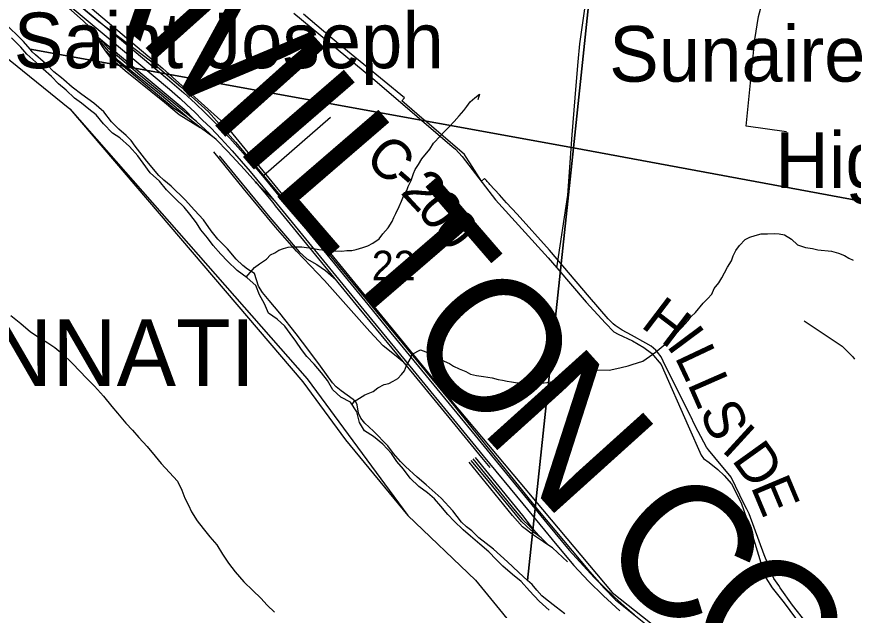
# Model space of a CAD drawing. Extents: x 0 to 34, y 0 to 22.
# Drawn here: x 5.729 to 6.917, y 14.739 to 15.582 of the extents above; entities that cross this region are included whole.
import ezdxf

# ---------------------------------------------------------------- set-up
doc = ezdxf.new("R2010")
doc.units = 0
for name, color, linetype in [('GM_X_City_Street', 7, 'Continuous'), ('GM_X_Corporation', 7, 'Continuous'), ('GM_X_Corporation_Text', 7, 'Continuous'), ('GM_X_County_Road', 7, 'Continuous'), ('GM_X_County_Road_Text', 7, 'Continuous'), ('GM_X_County_Text', 7, 'Continuous'), ('GM_X_Major_River', 7, 'Continuous'), ('GM_X_Minor_River', 7, 'Continuous'), ('GM_X_Rail_Line', 7, 'Continuous'), ('GM_X_Section_Text', 7, 'Continuous'), ('GM_X_Township_Road', 7, 'Continuous'), ('GM_X_Unincorporated_Text', 7, 'Continuous'), ('GM_X_US_Route', 7, 'Continuous')]:
    doc.layers.add(name, color=color, linetype=linetype)

msp = doc.modelspace()

# ---------------------------------------------------------------- linework, layer by layer
at = {"layer": 'GM_X_City_Street'}
msp.add_line((6.0794, 15.3568), (6.1746, 15.4398), dxfattribs=at)
at = {"layer": 'GM_X_Corporation'}
for points in [[(3.3535, 16.9293), (3.4766, 16.7367), (3.5579, 16.6419), (3.619, 16.5459), (3.7774, 16.2543), (3.8686, 16.1561), (3.9643, 16.0792), (4.2564, 15.9374), (4.3533, 15.9108), (4.4487, 15.8964), (4.6416, 15.8532), (4.7366, 15.8475), (5.0291, 15.8581), (5.1241, 15.8236), (5.4143, 15.7071), (5.7095, 15.5281), (5.8045, 15.4515), (6.1414, 15.0678), (6.2843, 14.8736), (6.3804, 14.7819), (6.459, 14.6859)], [(3.3535, 16.9293), (3.4766, 16.7367), (3.5579, 16.6419), (3.619, 16.5459), (3.7774, 16.2543), (3.8686, 16.1561), (3.9643, 16.0792), (4.2564, 15.9374), (4.3533, 15.9108), (4.4487, 15.8964), (4.6416, 15.8532), (4.7366, 15.8475), (5.0291, 15.8581), (5.1241, 15.8236), (5.4143, 15.7071), (5.7095, 15.5281), (5.8045, 15.4515), (6.1354, 15.0636), (6.1959, 14.9814), (6.2842, 14.8736), (6.3804, 14.7819), (6.459, 14.6859)], [(3.3535, 16.9293), (3.4766, 16.7367), (3.5579, 16.6419), (3.619, 16.5459), (3.7774, 16.2543), (3.8686, 16.1561), (3.9643, 16.0792), (4.2564, 15.9374), (4.3533, 15.9108), (4.4487, 15.8964), (4.6416, 15.8532), (4.7366, 15.8475), (5.0291, 15.8581), (5.1241, 15.8236), (5.4143, 15.7071), (5.7095, 15.5281), (5.8045, 15.4515), (6.1414, 15.0678), (6.2843, 14.8736), (6.3804, 14.7819), (6.459, 14.6859)], [(6.8502, 14.7219), (6.8308, 14.7465), (6.8133, 14.7711), (6.8111, 14.7743), (6.8041, 14.7841), (6.7996, 14.7951), (6.7955, 14.8053), (6.7903, 14.818), (6.769, 14.876), (6.7657, 14.8828), (6.7622, 14.8899), (6.7437, 14.9281), (6.7299, 14.9448), (6.7294, 14.9454), (6.7115, 14.9671), (6.7084, 14.971), (6.6966, 14.993), (6.691, 15.0041), (6.6865, 15.0133), (6.686, 15.0143), (6.6804, 15.0254), (6.6471, 15.093), (6.6439, 15.099), (6.639, 15.1059), (6.6366, 15.1085), (6.6334, 15.1114), (6.6297, 15.1142), (6.6222, 15.1186), (6.6021, 15.1298), (6.5887, 15.1372), (6.5828, 15.1407), (6.5788, 15.1436), (6.5757, 15.1461), (6.5687, 15.153), (6.5424, 15.184), (6.4856, 15.2508), (6.4394, 15.3019), (6.4246, 15.3181), (6.4145, 15.3292), (6.401, 15.344), (6.3997, 15.3454), (6.3984, 15.3468), (6.3971, 15.3483), (6.3958, 15.3497), (6.3945, 15.3511), (6.3933, 15.3525), (6.389, 15.3487), (6.3722, 15.375), (6.3715, 15.3761), (6.3713, 15.3763), (6.367, 15.3831), (6.3647, 15.3868), (6.3112, 15.4324), (6.3041, 15.4384), (6.2756, 15.4628), (6.2794, 15.467), (6.222, 15.5144), (6.1857, 15.5437), (6.1644, 15.5619), (6.1363, 15.5862)], [(6.5071, 14.734), (6.4952, 14.7437), (6.48, 14.7555), (6.4748, 14.7598), (6.4674, 14.7675), (6.4608, 14.776), (6.4541, 14.7815), (6.5194, 15.3963), (7.5438, 15.2065), (7.4624, 14.2167)]]:
    msp.add_lwpolyline(points, dxfattribs=at)
for points in [[(6.6267, 16.412), (6.5194, 15.3963), (5.7481, 15.5362), (5.7385, 15.5474), (5.73, 15.556), (5.7193, 15.5661), (5.7119, 15.5735), (5.7045, 15.5805), (5.6956, 15.5879), (5.6844, 15.5969), (5.6733, 15.6058), (5.6644, 15.6136), (5.6543, 15.6226), (5.6473, 15.6288), (5.6384, 15.6362), (5.6358, 15.6382), (5.7092, 16.4608)], [(7.6501, 16.2281), (7.5438, 15.2065), (6.5194, 15.3963), (6.6267, 16.412)], [(6.5194, 15.3963), (6.4541, 14.7815), (6.4415, 14.7932), (6.426, 14.8079), (6.4059, 14.8262), (6.3851, 14.8419), (6.3751, 14.852), (6.3677, 14.8578), (6.3607, 14.8644), (6.3482, 14.8803), (6.3316, 14.8985), (6.3104, 14.9176), (6.2974, 14.9285), (6.2811, 14.9433), (6.2741, 14.9503), (6.2641, 14.9619), (6.2561, 14.9727), (6.2354, 14.9936), (6.2231, 15.0049), (6.2176, 15.0123), (6.2144, 15.0192), (6.2124, 15.0309), (6.2106, 15.0351), (6.2069, 15.0386), (6.1894, 15.0508), (6.1827, 15.0567), (6.1772, 15.0625), (6.1603, 15.086), (6.1438, 15.108), (6.1258, 15.1319), (6.1027, 15.1613), (6.0876, 15.1794), (6.078, 15.1907), (6.0722, 15.1995), (6.0665, 15.2178), (6.0568, 15.2238), (6.0498, 15.2292), (6.0405, 15.2378), (6.0284, 15.2529), (6.0224, 15.2583), (6.0147, 15.2665), (6.0051, 15.2781), (5.9941, 15.2938), (5.9812, 15.3074), (5.9679, 15.3225), (5.9483, 15.3419), (5.9379, 15.3501), (5.9309, 15.3568), (5.9136, 15.3773), (5.897, 15.3985), (5.8916, 15.4066), (5.8845, 15.4136), (5.8738, 15.4229), (5.8634, 15.433), (5.8524, 15.4473), (5.8383, 15.4594), (5.8215, 15.4719), (5.8074, 15.4825), (5.7959, 15.493), (5.7926, 15.4957), (5.7814, 15.504), (5.7718, 15.5144), (5.7666, 15.5187), (5.7555, 15.5281), (5.7507, 15.5327), (5.7481, 15.5362)]]:
    msp.add_lwpolyline(points, close=True, dxfattribs=at)
at = {"layer": 'GM_X_County_Road'}
for points in [[(6.5262, 15.5183), (6.5284, 15.5439), (6.5532, 15.7171)], [(6.1224, 15.5873), (6.2346, 15.4946), (6.347, 15.3985), (6.3522, 15.3945), (6.3615, 15.3837), (6.4087, 15.3224), (6.4835, 15.24), (6.4957, 15.2258), (6.5378, 15.177), (6.5652, 15.1472), (6.5771, 15.1348), (6.5831, 15.1316), (6.6034, 15.1221), (6.6195, 15.1123), (6.6303, 15.1044), (6.644, 15.0882), (6.6823, 15.0013), (6.7011, 14.9596), (6.7044, 14.9549), (6.7122, 14.9491), (6.7245, 14.9393), (6.7334, 14.9308), (6.7438, 14.9188), (6.7576, 14.8916), (6.774, 14.8454), (6.7889, 14.7957), (6.7928, 14.7854), (6.8016, 14.7712), (6.8186, 14.7496), (6.8606, 14.6933)], [(6.4957, 15.2258), (6.5116, 15.3289), (6.5175, 15.4145), (6.5233, 15.4846), (6.5262, 15.5183)]]:
    msp.add_lwpolyline(points, dxfattribs=at)
at = {"layer": 'GM_X_Major_River'}
for points in [[(5.9843, 15.2894), (5.9747, 15.3017), (5.9669, 15.3121), (5.9545, 15.3237), (5.9418, 15.3364), (5.9314, 15.3487), (5.9183, 15.3607), (5.9083, 15.3742), (5.9009, 15.3849), (5.8889, 15.398), (5.8755, 15.4104), (5.865, 15.417), (5.8519, 15.4305), (5.8415, 15.4432), (5.8313, 15.4509), (5.8209, 15.4598), (5.8111, 15.4668), (5.7992, 15.478), (5.7883, 15.4873), (5.7782, 15.4977), (5.7666, 15.5081), (5.7558, 15.5178), (5.7434, 15.5294), (5.7349, 15.539), (5.7214, 15.5525)], [(6.4848, 14.7391), (6.4709, 14.7522), (6.4571, 14.7669), (6.4452, 14.78), (6.4328, 14.79), (6.4194, 14.802), (6.4097, 14.8113), (6.3992, 14.8224), (6.3865, 14.8333), (6.3734, 14.8445), (6.3629, 14.8534), (6.3502, 14.8657), (6.3412, 14.8754), (6.3312, 14.8873), (6.3222, 14.8977), (6.3121, 14.9062), (6.2998, 14.9151), (6.2874, 14.9267), (6.2781, 14.9397), (6.2688, 14.9505), (6.261, 14.9617), (6.2487, 14.9751), (6.2356, 14.986), (6.2229, 14.9941), (6.2155, 15.006), (6.2119, 15.0209), (6.203, 15.0347), (6.1891, 15.0417), (6.1779, 15.0522), (6.1701, 15.0656), (6.1619, 15.0767), (6.1515, 15.0886), (6.1411, 15.0998), (6.1333, 15.1098), (6.1251, 15.1217), (6.1173, 15.1325), (6.1095, 15.1428), (6.0987, 15.1529), (6.0863, 15.1614), (6.0808, 15.1744), (6.0738, 15.1874), (6.0683, 15.2004), (6.056, 15.2116), (6.0417, 15.2217), (6.0283, 15.2352), (6.0189, 15.2449), (6.0077, 15.2572), (5.9999, 15.2683), (5.9903, 15.2799), (5.9843, 15.2894)], [(5.7205, 15.1581), (5.7348, 15.1465), (5.7482, 15.1349), (5.7595, 15.1275), (5.773, 15.1193), (5.7828, 15.1124), (5.794, 15.1034), (5.8082, 15.0896), (5.8187, 15.0788), (5.828, 15.0687), (5.8392, 15.0576), (5.8523, 15.0433), (5.8638, 15.0287), (5.872, 15.0191), (5.8839, 15.0052), (5.8932, 14.9952), (5.9022, 14.9844), (5.9141, 14.9717), (5.9253, 14.9579), (5.9342, 14.9479), (5.9458, 14.9348), (5.957, 14.9228), (5.9632, 14.9098), (5.9676, 14.8984), (5.9727, 14.8884), (5.9771, 14.8789), (5.9853, 14.8662), (5.9938, 14.8555), (6.0031, 14.8435), (6.0132, 14.832), (6.021, 14.819), (6.0295, 14.8059), (6.0391, 14.7936), (6.0514, 14.7798), (6.0642, 14.7674), (6.0757, 14.7562), (6.0847, 14.7466), (6.0948, 14.7366)]]:
    msp.add_lwpolyline(points, dxfattribs=at)
at = {"layer": 'GM_X_Minor_River'}
for points in [[(6.0548, 15.2124), (6.0667, 15.2262), (6.0737, 15.2314), (6.0837, 15.2381), (6.0892, 15.2441), (6.0953, 15.247), (6.1011, 15.2507), (6.1077, 15.2532), (6.1142, 15.255), (6.1207, 15.2556), (6.1337, 15.2554), (6.1402, 15.2545), (6.1482, 15.2536), (6.1581, 15.2519), (6.1676, 15.2506), (6.1764, 15.2497), (6.1905, 15.2495), (6.1977, 15.2501), (6.205, 15.2503), (6.2111, 15.2518), (6.2204, 15.2546), (6.2277, 15.2568), (6.2346, 15.2605), (6.2435, 15.2668), (6.2486, 15.2739), (6.2564, 15.2825), (6.2623, 15.2915), (6.2643, 15.2972), (6.2674, 15.3028), (6.2722, 15.313), (6.2754, 15.3202), (6.2782, 15.3273), (6.2829, 15.3356), (6.2849, 15.3413), (6.2889, 15.3499), (6.2925, 15.3598), (6.2949, 15.3654), (6.2993, 15.3726), (6.3044, 15.3805), (6.3157, 15.3943), (6.3208, 15.4026), (6.3306, 15.4131), (6.336, 15.4187), (6.343, 15.4258), (6.35, 15.4336), (6.3574, 15.4415), (6.3637, 15.4493), (6.368, 15.455), (6.3727, 15.4613), (6.3797, 15.4673), (6.3859, 15.4725), (6.3838, 15.4642)], [(6.2051, 15.0314), (6.208, 15.0359), (6.2157, 15.0403), (6.2234, 15.0451), (6.2353, 15.0502), (6.2415, 15.0551), (6.2508, 15.0599), (6.2573, 15.0613), (6.2635, 15.0649), (6.27, 15.0683), (6.2755, 15.0739), (6.2798, 15.0795), (6.2826, 15.0867), (6.2874, 15.0961), (6.2905, 15.1029), (6.3025, 15.1091), (6.3101, 15.1063), (6.3191, 15.1016), (6.3248, 15.0984), (6.3316, 15.0949), (6.3434, 15.0897), (6.349, 15.0862), (6.357, 15.0823), (6.3665, 15.0783), (6.3733, 15.0748), (6.382, 15.0727), (6.3919, 15.0714), (6.4041, 15.0693), (6.4125, 15.0672), (6.4189, 15.066), (6.4254, 15.0647), (6.4315, 15.0638), (6.4372, 15.063), (6.4456, 15.0617), (6.4536, 15.0604), (6.4616, 15.0603), (6.4677, 15.0605), (6.4746, 15.0619), (6.4819, 15.0629), (6.4876, 15.0636), (6.4945, 15.0646), (6.501, 15.0649), (6.5072, 15.0663), (6.516, 15.068), (6.5229, 15.0725), (6.531, 15.0765), (6.5379, 15.0798), (6.5452, 15.0804), (6.5517, 15.0807), (6.5704, 15.0804), (6.5811, 15.0825), (6.5873, 15.0839), (6.5973, 15.0863), (6.603, 15.0885), (6.6107, 15.0907), (6.618, 15.0932), (6.6277, 15.0995), (6.6362, 15.1058), (6.6494, 15.1166), (6.6552, 15.1233), (6.6637, 15.1304), (6.6739, 15.1416), (6.6824, 15.151), (6.6867, 15.1566), (6.693, 15.1622), (6.7039, 15.1753), (6.7101, 15.1816), (6.716, 15.1884), (6.7195, 15.1963), (6.7258, 15.2045), (6.7301, 15.2113), (6.7341, 15.2185), (6.7384, 15.2264), (6.7439, 15.2358), (6.7464, 15.2429), (6.7503, 15.2501), (6.7554, 15.2572), (6.7632, 15.2658), (6.7701, 15.2691), (6.7774, 15.2717), (6.7859, 15.2738), (6.795, 15.274), (6.8046, 15.2746), (6.8115, 15.2741), (6.8191, 15.2724), (6.8293, 15.2665), (6.8375, 15.2584), (6.8489, 15.2548), (6.8588, 15.2531), (6.8668, 15.2514), (6.8859, 15.2492), (6.8961, 15.2463), (6.9045, 15.2432), (6.9105, 15.2392), (6.9169, 15.2365)]]:
    msp.add_lwpolyline(points, dxfattribs=at)
at = {"layer": 'GM_X_Rail_Line'}
for p, q in [((5.8404, 15.5568), (5.8328, 15.5675)), ((5.9895, 15.4249), (5.972, 15.4389)), ((6.4737, 14.842), (6.4847, 14.8311))]:
    msp.add_line(p, q, dxfattribs=at)
for points in [[(4.6314, 16.1011), (4.6907, 16.0865), (4.93, 15.9918), (5.1919, 15.9535), (5.3649, 15.9246), (5.4749, 15.8856), (5.5993, 15.8085), (5.7206, 15.6918), (5.9364, 15.509), (6.0231, 15.4314), (6.3347, 15.0503), (6.5747, 14.7642), (6.7584, 14.6191)], [(5.7122, 15.6751), (5.7619, 15.634), (5.8503, 15.5596), (5.9458, 15.4793), (5.9608, 15.4661), (5.9704, 15.4574), (5.9817, 15.447), (5.9929, 15.4357), (6.0045, 15.4244), (6.019, 15.4091), (6.0349, 15.3918), (6.0602, 15.3627), (6.0987, 15.316), (6.2175, 15.1708), (6.2955, 15.0757), (6.3492, 15.0101), (6.3914, 14.9584), (6.4474, 14.8905), (6.4959, 14.8316), (6.5203, 14.8027), (6.5411, 14.7807), (6.5624, 14.7596), (6.5852, 14.7386)], [(5.7213, 15.6798), (5.7557, 15.6511), (5.8511, 15.5715), (5.943, 15.4944), (5.966, 15.4741), (5.9828, 15.459), (5.9963, 15.4461), (6.0138, 15.4286), (6.0316, 15.4101), (6.0506, 15.3886), (6.078, 15.3562), (6.1264, 15.2973), (6.2276, 15.1735), (6.2604, 15.1335), (6.3755, 14.9928), (6.4815, 14.863), (6.5134, 14.8244), (6.5336, 14.8022), (6.549, 14.7859), (6.5612, 14.7737), (6.5779, 14.7577), (6.5921, 14.745), (6.606, 14.7327)], [(5.8328, 15.5675), (5.823, 15.5766), (5.8067, 15.5911), (5.7535, 15.6359), (5.7303, 15.6602)], [(5.845, 15.5531), (5.8331, 15.5672), (5.8328, 15.5675)], [(5.972, 15.4389), (5.9703, 15.4402), (5.9315, 15.4729), (5.8735, 15.5196), (5.8587, 15.5342), (5.8431, 15.5529), (5.8404, 15.5568)], [(5.8404, 15.5568), (5.8502, 15.5402), (5.8535, 15.5356)], [(5.9823, 15.4349), (5.9446, 15.4659), (5.9071, 15.4964), (5.8591, 15.5373), (5.8469, 15.5509), (5.845, 15.5531)], [(5.845, 15.5531), (5.8983, 15.508), (5.9667, 15.451), (5.9823, 15.4349)], [(5.972, 15.4389), (5.9512, 15.4528), (5.9123, 15.4854), (5.8718, 15.5186), (5.8535, 15.5356)], [(5.8535, 15.5356), (5.8614, 15.5246), (5.8829, 15.5061), (5.9385, 15.461), (5.9596, 15.4434), (5.9895, 15.4249)], [(6.0092, 15.4106), (5.9841, 15.4334), (5.9823, 15.4349)], [(6.0092, 15.4106), (5.9911, 15.4236), (5.9895, 15.4249)], [(6.0678, 15.3477), (6.0522, 15.3655), (6.0287, 15.391), (6.0122, 15.4079), (6.0092, 15.4106)], [(6.2786, 15.091), (6.2654, 15.1022), (6.2492, 15.1148), (6.2302, 15.1352), (6.1659, 15.2075), (6.1261, 15.2494), (6.0965, 15.2836), (6.0507, 15.3384), (6.0086, 15.3903)], [(6.0165, 15.3847), (6.0881, 15.2974), (6.1298, 15.2482), (6.1407, 15.2384), (6.155, 15.2304), (6.1672, 15.2217), (6.1824, 15.2084)], [(6.0931, 15.3229), (6.0693, 15.346), (6.0678, 15.3477)], [(6.0678, 15.3477), (6.0925, 15.3183), (6.0961, 15.3139), (6.2149, 15.1686), (6.2929, 15.0736), (6.3466, 15.0079), (6.3888, 14.9563), (6.4006, 14.9419)], [(6.4847, 14.8311), (6.4768, 14.8366), (6.4626, 14.8461), (6.4472, 14.8579), (6.4328, 14.8736), (6.3712, 14.9494)], [(6.4737, 14.842), (6.4589, 14.8529), (6.4458, 14.8654), (6.4009, 14.92), (6.3743, 14.9519)], [(6.3764, 14.9542), (6.4367, 14.8803), (6.447, 14.8683), (6.4664, 14.8497)], [(6.3798, 14.9561), (6.447, 14.8739), (6.4593, 14.8577), (6.4664, 14.8497)], [(6.4664, 14.8497), (6.4702, 14.8454), (6.4737, 14.842)], [(6.5112, 14.8082), (6.4897, 14.8277), (6.4847, 14.8311)]]:
    msp.add_lwpolyline(points, dxfattribs=at)
at = {"layer": 'GM_X_Township_Road'}
for points in [[(6.8221, 15.4189), (6.765, 15.4269), (6.7772, 15.55), (6.7823, 15.5827), (6.7908, 15.6146), (6.802, 15.6483)], [(6.8471, 15.1505), (6.9013, 15.1146), (6.9163, 15.0994), (6.9189, 15.0957)]]:
    msp.add_lwpolyline(points, dxfattribs=at)
at = {"layer": 'GM_X_US_Route'}
msp.add_lwpolyline([(5.6607, 15.7259), (5.6849, 15.7062), (5.7001, 15.6939), (5.7736, 15.6359), (5.8456, 15.5757), (5.9188, 15.5196), (5.9615, 15.4831), (6.0011, 15.4472), (6.0397, 15.4044), (6.0794, 15.3568), (6.1454, 15.2774), (6.3518, 15.0271), (6.4684, 14.8825), (6.5421, 14.7942), (6.563, 14.7705), (6.5793, 14.7538), (6.6291, 14.714)], dxfattribs=at)

# ---------------------------------------------------------------- texts
at = {"layer": 'GM_X_Corporation_Text'}
msp.add_text('CINCINNATI', height=0.0947, rotation=0, dxfattribs=at).set_placement((5.3431, 15.0576))
at = {"layer": 'GM_X_County_Road_Text'}
for s, rotation, p in [('C', 319.2139, (6.2207, 15.3771)), ('-', 319.0935, (6.256, 15.3467)), ('2', 312.9177, (6.2725, 15.3325)), ('0', 307.5152, (6.2954, 15.308)), ('0', 309.2083, (6.3178, 15.2788)), ('H', 322.7635, (6.6135, 15.1427)), ('I', 306.7122, (6.6503, 15.1154)), ('L', 295.2837, (6.6627, 15.0993)), ('L', 293.7034, (6.6807, 15.0612)), ('S', 293.5899, (6.6978, 15.0223)), ('I', 317.5313, (6.7281, 14.9663)), ('D', 305.5868, (6.7432, 14.9528)), ('E', 292.7395, (6.7707, 14.9151))]:
    msp.add_text(s, height=0.0568, rotation=rotation, dxfattribs=at).set_placement(p)
at = {"layer": 'GM_X_County_Text'}
for s, rotation, p in [('A', 320.9905, (5.7737, 15.6534)), ('M', 311.8731, (5.8981, 15.5535)), ('I', 310.852, (6.0349, 15.4009)), ('L', 310.7782, (6.0855, 15.3423)), ('T', 310.7744, (6.1781, 15.235)), ('O', 310.9226, (6.2709, 15.1273)), ('N', 312.0598, (6.3834, 14.9977)), ('C', 315.9774, (6.5454, 14.8218)), ('O', 318.4967, (6.6629, 14.7085))]:
    msp.add_text(s, height=0.1894, rotation=rotation, dxfattribs=at).set_placement(p)
at = {"layer": 'GM_X_Section_Text'}
msp.add_text('22', height=0.04186, rotation=0, dxfattribs=at).set_placement((6.2331, 15.2081))
at = {"layer": 'GM_X_Unincorporated_Text'}
for s, height, p in [('Mount Saint Joseph', 0.078977, (5.4018, 15.5093)), ('Sunaire', 0.07898, (6.5702, 15.4902)), ('Highland Park', 0.078977, (6.806, 15.3393))]:
    msp.add_text(s, height=height, rotation=0, dxfattribs=at).set_placement(p)

doc.saveas('drawing.dxf')
